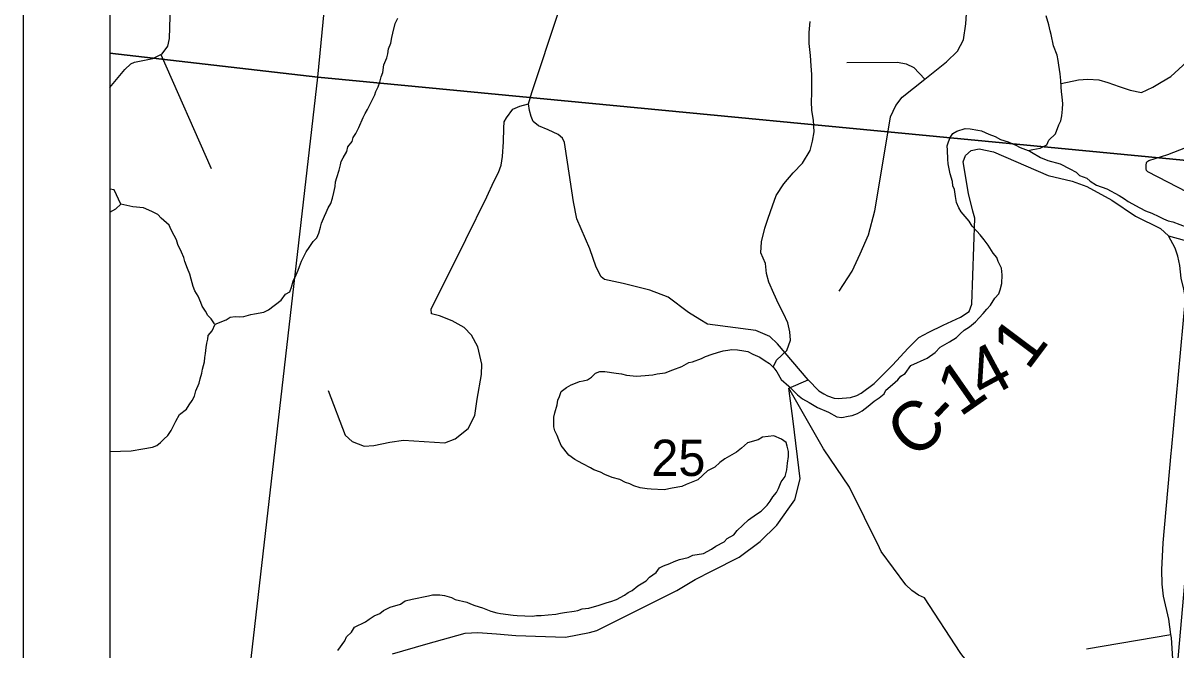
# Model space of a CAD drawing. Extents: x 0 to 34, y -2 to 22.
# Drawn here: x 2 to 3.329, y 18.423 to 19.146 of the extents above; entities that cross this region are included whole.
import ezdxf

# ---------------------------------------------------------------- set-up
doc = ezdxf.new("R2010")
doc.units = 0
for name, color, linetype in [('Default', 7, 'Continuous'), ('GM_X_County_Road', 7, 'Continuous'), ('GM_X_County_Road_Text', 7, 'Continuous'), ('GM_X_Minor_Lake', 7, 'Continuous'), ('GM_X_Minor_River', 7, 'Continuous'), ('GM_X_Rail_Line', 7, 'Continuous'), ('GM_X_Section', 7, 'Continuous'), ('GM_X_Section_Text', 7, 'Continuous'), ('GM_X_Township_Road', 7, 'Continuous'), ('SH_Cut_Line', 7, 'Continuous'), ('SH_Data', 7, 'Continuous')]:
    doc.layers.add(name, color=color, linetype=linetype)

msp = doc.modelspace()

# ---------------------------------------------------------------- linework, layer by layer
at = {"layer": 'Default'}
for points in [[(2.1, 20.1369), (2.1, 19.1108), (2.3398, 19.083), (2.4387, 20.1012)], [(2.1, 19.1108), (2.1, 18.1402), (2.2302, 18.1283), (2.3398, 19.083)]]:
    msp.add_lwpolyline(points, close=True, dxfattribs=at)
at = {"layer": 'GM_X_County_Road'}
for p, q in [((2.883, 18.7247), (2.9052, 18.7343)), ((2.8877, 18.6867), (2.883, 18.7247))]:
    msp.add_line(p, q, dxfattribs=at)
for points in [[(2.1, 19.0714), (2.1174, 19.092), (2.1244, 19.0986), (2.1286, 19.1004), (2.1496, 19.1047), (2.1589, 19.1093), (2.1604, 19.11), (2.1668, 19.1189), (2.1689, 19.1276), (2.1712, 19.2042)], [(2.9052, 18.7343), (2.8698, 18.7757), (2.861, 18.7844), (2.8449, 18.791), (2.7891, 18.7985), (2.7801, 18.8037), (2.7671, 18.8117), (2.7438, 18.8295), (2.7225, 18.8375), (2.692, 18.8453), (2.6705, 18.8498), (2.6665, 18.8529), (2.6608, 18.8641), (2.6535, 18.8854), (2.6386, 18.9199), (2.6348, 18.9394), (2.6277, 18.985), (2.6241, 19.0078), (2.6218, 19.0128), (2.6171, 19.0171), (2.6053, 19.0224), (2.5942, 19.0272), (2.5883, 19.0321), (2.5859, 19.038), (2.584, 19.0447), (2.5829, 19.0523), (2.5867, 19.0654), (2.6175, 19.1582)], [(3.2954, 18.9847), (3.2957, 18.9857), (3.298, 18.9872), (3.3198, 18.9941), (3.3543, 19.0075), (3.3733, 19.0175), (3.3749, 19.0196), (3.3759, 19.0213), (3.3764, 19.0222)], [(2.9052, 18.7343), (2.9175, 18.7215), (2.9232, 18.7181), (2.9276, 18.716), (2.9353, 18.7132), (2.9398, 18.7126), (2.9539, 18.7138), (2.9613, 18.7163), (2.9662, 18.7187), (2.9813, 18.73), (3.0025, 18.7513), (3.0206, 18.7709), (3.0327, 18.783), (3.0443, 18.7891), (3.0609, 18.7973), (3.0809, 18.8066), (3.0906, 18.8131), (3.0939, 18.8213), (3.0975, 18.9207), (3.0951, 18.9288), (3.0901, 18.9491), (3.0837, 18.9854), (3.0866, 18.9929), (3.0932, 18.9988), (3.1024, 19.0004), (3.1189, 18.9972), (3.1817, 18.9697), (3.2096, 18.9631), (3.2265, 18.9572), (3.2551, 18.9415), (3.2826, 18.9228), (3.3113, 18.9086), (3.3205, 18.9003)], [(3.3715, 18.9091), (3.3743, 18.9185), (3.374, 18.9246), (3.3728, 18.9294), (3.3698, 18.934), (3.3693, 18.9347), (3.3678, 18.9363), (3.3542, 18.9444), (3.2968, 18.974), (3.2952, 18.9755), (3.295, 18.9775), (3.2948, 18.9828), (3.2951, 18.9838), (3.2954, 18.9847)], [(3.3205, 18.9003), (3.3385, 18.8951), (3.3495, 18.8937), (3.3545, 18.8947), (3.3715, 18.9091)], [(3.324, 18.6527), (3.3401, 18.8282), (3.3382, 18.8386), (3.3352, 18.8516), (3.3338, 18.866), (3.3315, 18.8768), (3.3284, 18.886), (3.3205, 18.9003)], [(2.9873, 18.5407), (2.9529, 18.6106), (2.9227, 18.6546), (2.883, 18.7247)], [(2.7943, 18.5139), (2.8257, 18.53), (2.8499, 18.548), (2.869, 18.5667), (2.884, 18.588), (2.8896, 18.596), (2.896, 18.6203), (2.8877, 18.6867)], [(3.2876, 17.9648), (3.2993, 18.0896), (3.3169, 18.29), (3.3244, 18.3467), (3.3252, 18.3831), (3.3254, 18.4128), (3.3239, 18.4367), (3.3234, 18.4405), (3.3209, 18.4585), (3.3149, 18.4849), (3.3131, 18.4986), (3.3129, 18.5153), (3.3143, 18.5465), (3.3238, 18.6498), (3.324, 18.6527)], [(3.3169, 18.29), (3.2265, 18.2864), (3.219, 18.2885), (3.2101, 18.2938), (3.1687, 18.3312), (3.1088, 18.3855), (3.0822, 18.4172), (3.0803, 18.42), (3.0392, 18.4831), (3.0325, 18.486), (3.0247, 18.4912), (3.0177, 18.4979), (2.9894, 18.5364), (2.9873, 18.5407)], [(2.4259, 18.4185), (2.4645, 18.4294), (2.5099, 18.4421), (2.5243, 18.4429), (2.5459, 18.4413), (2.5682, 18.4397), (2.6023, 18.4382), (2.6254, 18.4377), (2.6532, 18.4428), (2.6617, 18.4452), (2.6662, 18.4474), (2.7539, 18.4914), (2.7749, 18.5039), (2.7943, 18.5139)]]:
    msp.add_lwpolyline(points, dxfattribs=at)
at = {"layer": 'GM_X_Minor_Lake'}
for points in [[(2.1129, 18.9369), (2.105, 18.9534), (2.1, 18.954)], [(2.1, 18.9275), (2.1071, 18.9313), (2.1129, 18.9369)]]:
    msp.add_lwpolyline(points, dxfattribs=at)
at = {"layer": 'GM_X_Minor_River'}
for points in [[(2.9511, 18.6922), (2.9557, 18.6932), (2.9619, 18.6956), (2.9673, 18.6985), (2.9743, 18.7039), (2.9813, 18.7098), (2.9871, 18.7134), (2.9926, 18.7181), (2.9947, 18.7222), (3.0025, 18.7288), (3.0084, 18.7343), (3.0119, 18.7384), (3.017, 18.7416), (3.0234, 18.7509), (3.0423, 18.7594), (3.0516, 18.7659), (3.0575, 18.7718), (3.068, 18.7779), (3.0761, 18.7829), (3.0804, 18.7873), (3.0851, 18.7917), (3.091, 18.7953), (3.098, 18.8011), (3.1023, 18.8059), (3.1071, 18.8107), (3.111, 18.8159), (3.1154, 18.8203), (3.1202, 18.8285), (3.1249, 18.8333), (3.1266, 18.8382), (3.1284, 18.8453), (3.1287, 18.8552), (3.1279, 18.8628), (3.1243, 18.8706), (3.1226, 18.8752), (3.1186, 18.8803), (3.1128, 18.8896), (3.1081, 18.8958), (3.1034, 18.9013), (3.0997, 18.9056), (3.0942, 18.9115), (3.0906, 18.9173), (3.0815, 18.9279), (3.079, 18.9326), (3.0762, 18.9387), (3.0749, 18.9456), (3.074, 18.9536), (3.0719, 18.9579), (3.0717, 18.9628), (3.069, 18.9717), (3.0667, 18.9832), (3.0661, 18.9885), (3.0657, 18.9992), (3.0655, 19.0041), (3.0668, 19.0086), (3.0689, 19.0135), (3.0721, 19.0183), (3.0767, 19.0208), (3.086, 19.0239), (3.092, 19.0237), (3.1007, 19.0219), (3.1049, 19.0214), (3.1134, 19.0173), (3.1206, 19.0147), (3.1269, 19.0115), (3.1359, 19.0085), (3.14, 19.0068), (3.1445, 19.0048), (3.1494, 19.002), (3.1587, 18.9986), (3.1641, 18.9996), (3.1725, 19.0012), (3.1802, 19.0051), (3.1827, 19.0107), (3.1902, 19.018), (3.1943, 19.0282), (3.1964, 19.033), (3.1977, 19.0387), (3.1984, 19.0463), (3.1986, 19.0527), (3.1981, 19.0603), (3.1972, 19.0668), (3.197, 19.0718), (3.1965, 19.0794), (3.1956, 19.087), (3.194, 19.097), (3.1935, 19.1023), (3.1921, 19.1084), (3.188, 19.1192), (3.1854, 19.1322), (3.184, 19.1365), (3.1827, 19.1434), (3.1797, 19.1537)], [(2.1, 18.6516), (2.1122, 18.6521), (2.1247, 18.6524), (2.1381, 18.6546), (2.1492, 18.6565), (2.1542, 18.6586), (2.1585, 18.6619), (2.1624, 18.6659), (2.1671, 18.6699), (2.1707, 18.6759), (2.1732, 18.6804), (2.176, 18.6867), (2.1805, 18.6942), (2.1886, 18.7004), (2.1915, 18.7056), (2.1951, 18.7104), (2.1975, 18.7156), (2.1993, 18.7217), (2.203, 18.7303), (2.2043, 18.7355), (2.206, 18.7419), (2.2069, 18.7465), (2.2091, 18.7551), (2.2097, 18.7601), (2.2102, 18.7646), (2.2112, 18.7714), (2.2118, 18.7767), (2.2131, 18.7812), (2.2136, 18.7854), (2.218, 18.7909), (2.2216, 18.7984), (2.234, 18.8033), (2.2386, 18.8066), (2.2444, 18.8071), (2.2497, 18.807), (2.2546, 18.8072), (2.2627, 18.8095), (2.2669, 18.8105), (2.2776, 18.8124), (2.283, 18.8149), (2.2974, 18.8262), (2.3026, 18.8332), (2.3076, 18.8357), (2.3093, 18.841), (2.3114, 18.8481), (2.3147, 18.8553), (2.3172, 18.8605), (2.3189, 18.865), (2.321, 18.871), (2.3263, 18.8818), (2.3299, 18.887), (2.3343, 18.8937), (2.3386, 18.8981), (2.3411, 18.9034), (2.3428, 18.9102), (2.3441, 18.9147), (2.3474, 18.9229), (2.3495, 18.927), (2.3516, 18.9327), (2.3548, 18.9375), (2.3569, 18.9435), (2.3583, 18.9503), (2.36, 18.9571), (2.3602, 18.9624), (2.3619, 18.9677), (2.3645, 18.9759), (2.3658, 18.982), (2.3667, 18.9861), (2.3691, 18.9902), (2.3732, 18.9973), (2.3745, 19.003), (2.3793, 19.0092), (2.3806, 19.0138), (2.3838, 19.0182), (2.387, 19.0253), (2.392, 19.0366), (2.3944, 19.0414), (2.3973, 19.0459), (2.4013, 19.0545), (2.4054, 19.0627), (2.4067, 19.0668), (2.4095, 19.0721), (2.4112, 19.0773), (2.413, 19.0837), (2.4147, 19.0886), (2.4161, 19.0973), (2.4194, 19.1055), (2.4204, 19.1101), (2.4213, 19.1157), (2.4242, 19.1225), (2.4252, 19.1289), (2.4265, 19.1338), (2.4292, 19.1451), (2.432, 19.1511)], [(2.865, 18.7487), (2.8686, 18.757), (2.8806, 18.768), (2.8848, 18.7801), (2.8839, 18.7896), (2.8816, 18.7999), (2.8766, 18.8107), (2.8708, 18.8219), (2.8655, 18.8339), (2.8598, 18.8469), (2.857, 18.8569), (2.8558, 18.8683), (2.8505, 18.8807), (2.8512, 18.8932), (2.8551, 18.909), (2.8589, 18.9207), (2.8642, 18.935), (2.8683, 18.9467), (2.8771, 18.9601), (2.8877, 18.9727), (2.8987, 18.9842), (2.9075, 18.9988), (2.91, 19.0094), (2.9119, 19.0203), (2.9115, 19.0337), (2.9095, 19.0447), (2.9091, 19.055), (2.9094, 19.0645), (2.9093, 19.0759), (2.9092, 19.0862), (2.9087, 19.0961), (2.908, 19.1083), (2.9065, 19.122), (2.9064, 19.1346), (2.9076, 19.1475)], [(3.1967, 19.076), (3.2167, 19.0801), (3.2277, 19.0809), (3.2402, 19.0802), (3.2508, 19.0772), (3.2639, 19.0726), (3.2763, 19.0681), (3.2896, 19.0654), (3.3026, 19.0715), (3.3123, 19.0773), (3.3231, 19.0839), (3.3372, 19.0968), (3.3493, 19.1097), (3.3615, 19.1223), (3.3766, 19.134), (3.39, 19.1386), (3.4031, 19.1439)], [(3.1595, 18.9987), (3.1628, 18.9966), (3.1729, 18.9905), (3.1815, 18.9872), (3.1958, 18.9833), (3.207, 18.9775), (3.2141, 18.9735), (3.2181, 18.9699), (3.2264, 18.9666), (3.2304, 18.9634), (3.2375, 18.9586), (3.2495, 18.9544), (3.2636, 18.9467), (3.27, 18.9431), (3.274, 18.9399), (3.2874, 18.9326), (3.2941, 18.9289), (3.3013, 18.9264), (3.3095, 18.9227), (3.3147, 18.9198), (3.3203, 18.9177), (3.3256, 18.9164), (3.3417, 18.9102)], [(2.1547, 18.9254), (2.1484, 18.9283), (2.1387, 18.9324), (2.1265, 18.9338), (2.1129, 18.9369)], [(2.2209, 18.7988), (2.2169, 18.8047), (2.2129, 18.8086), (2.2104, 18.8133), (2.2064, 18.8191), (2.205, 18.8233), (2.2019, 18.8307), (2.1979, 18.8369), (2.1962, 18.8419), (2.1938, 18.8503), (2.1921, 18.8561), (2.1897, 18.8626), (2.1866, 18.8707), (2.1852, 18.8753), (2.1828, 18.8815), (2.1785, 18.8904), (2.1768, 18.8958), (2.1743, 18.9008), (2.1707, 18.907), (2.1683, 18.9124), (2.1594, 18.9207), (2.1554, 18.925), (2.1547, 18.9254)], [(2.8741, 18.6166), (2.8785, 18.6229), (2.8806, 18.6304), (2.8813, 18.638), (2.8823, 18.6459), (2.8825, 18.6516), (2.8808, 18.6578), (2.8798, 18.662), (2.8743, 18.666), (2.8657, 18.6697), (2.8527, 18.6682), (2.8477, 18.665), (2.8354, 18.6616), (2.8283, 18.6554), (2.8225, 18.651), (2.8089, 18.6431), (2.8035, 18.6388), (2.7976, 18.6337), (2.7891, 18.6294), (2.7781, 18.6191), (2.7646, 18.6135), (2.7596, 18.6114), (2.7482, 18.6095), (2.739, 18.6076), (2.7242, 18.6081), (2.7197, 18.6086), (2.7113, 18.6097), (2.7042, 18.6122), (2.6994, 18.6143), (2.6945, 18.6159), (2.6881, 18.6192), (2.6791, 18.6218), (2.6709, 18.6251), (2.6657, 18.628), (2.6582, 18.6305), (2.6541, 18.6329), (2.6455, 18.6374), (2.6403, 18.6402), (2.6362, 18.6423), (2.6291, 18.6475), (2.6204, 18.6584), (2.6176, 18.665), (2.6159, 18.67), (2.613, 18.6754), (2.612, 18.68), (2.6118, 18.6849), (2.612, 18.6914), (2.613, 18.6963), (2.6156, 18.7053), (2.6165, 18.711), (2.6186, 18.7151), (2.6203, 18.7208), (2.6265, 18.7255), (2.6319, 18.7283), (2.6369, 18.7304), (2.6415, 18.7322), (2.6458, 18.7332), (2.6507, 18.7342), (2.6554, 18.7374), (2.6601, 18.7418), (2.6651, 18.7439), (2.6708, 18.7437), (2.6837, 18.7421), (2.6901, 18.7412), (2.6957, 18.7398), (2.7074, 18.7386), (2.7173, 18.7391), (2.7215, 18.7397), (2.7261, 18.7399), (2.7311, 18.7413), (2.7402, 18.7425), (2.7491, 18.7456), (2.7595, 18.7498), (2.7676, 18.7541), (2.7718, 18.755), (2.7822, 18.7589), (2.7868, 18.761), (2.7945, 18.7638), (2.8006, 18.7658), (2.8072, 18.7675), (2.8125, 18.7685), (2.8171, 18.7691), (2.8235, 18.7688), (2.8311, 18.7678), (2.8356, 18.7669), (2.8412, 18.764), (2.8494, 18.7603), (2.8554, 18.756), (2.8606, 18.7531), (2.8657, 18.748), (2.869, 18.7433), (2.874, 18.7348), (2.8828, 18.7269), (2.8927, 18.717), (2.8986, 18.7123), (2.9065, 18.7082), (2.9158, 18.7025), (2.9285, 18.6968), (2.9382, 18.6915), (2.9438, 18.6909), (2.9511, 18.6922)], [(2.3628, 18.4222), (2.3711, 18.4333), (2.3728, 18.4378), (2.3787, 18.4433), (2.382, 18.4493), (2.3947, 18.4553), (2.399, 18.4585), (2.4048, 18.4621), (2.4113, 18.465), (2.4156, 18.4682), (2.4234, 18.4721), (2.4353, 18.4755), (2.4407, 18.4795), (2.4487, 18.4815), (2.4675, 18.4851), (2.4721, 18.4864), (2.4804, 18.4865), (2.4857, 18.4856), (2.494, 18.4834), (2.4981, 18.481), (2.5116, 18.4778), (2.5158, 18.4762), (2.521, 18.4741), (2.5296, 18.4715), (2.5394, 18.4677), (2.5461, 18.4656), (2.5503, 18.4647), (2.565, 18.4631), (2.5696, 18.4625), (2.5874, 18.4619), (2.592, 18.4625), (2.5973, 18.4627), (2.6053, 18.4632), (2.6144, 18.464), (2.6198, 18.4653), (2.6244, 18.4659), (2.6354, 18.4675), (2.6396, 18.4685), (2.6446, 18.4702), (2.6523, 18.4711), (2.6641, 18.4745), (2.6734, 18.4776), (2.6776, 18.4789), (2.6841, 18.481), (2.6934, 18.486), (2.6977, 18.4889), (2.7023, 18.4914), (2.7086, 18.4969), (2.7183, 18.5026), (2.7222, 18.5067), (2.73, 18.5121), (2.7336, 18.5177), (2.7382, 18.5198), (2.7455, 18.5226), (2.7506, 18.5247), (2.7567, 18.5271), (2.767, 18.5294), (2.7721, 18.5323), (2.7843, 18.5342), (2.7936, 18.5391), (2.7986, 18.5424), (2.8083, 18.5474), (2.8118, 18.5514), (2.8196, 18.5557), (2.8232, 18.5606), (2.8365, 18.573), (2.8455, 18.5792), (2.8509, 18.5828), (2.858, 18.5898), (2.8612, 18.5942), (2.8644, 18.5994), (2.8687, 18.6042), (2.8708, 18.6091), (2.8741, 18.6166)]]:
    msp.add_lwpolyline(points, dxfattribs=at)
at = {"layer": 'GM_X_Rail_Line'}
msp.add_lwpolyline([(7.5809, 20.9), (2.1, 20.9), (2.1, 18.1368), (2.3446, 18.1102), (2.9298, 18.0171), (3.2869, 17.9604), (3.6832, 17.9108)], dxfattribs=at)
at = {"layer": 'GM_X_Section'}
for points in [[(3.4541, 19.9967), (3.3818, 18.9832), (2.3398, 19.083), (2.4387, 20.1012)], [(2.3398, 19.083), (3.3818, 18.9832), (3.2914, 17.96), (2.2302, 18.1283)]]:
    msp.add_lwpolyline(points, close=True, dxfattribs=at)
at = {"layer": 'GM_X_Township_Road'}
for p, q in [((2.1589, 19.1093), (2.2168, 18.9779)), ((3.2261, 18.4243), (3.3234, 18.4405))]:
    msp.add_line(p, q, dxfattribs=at)
for points in [[(2.9408, 18.8365), (2.956, 18.8596), (2.965, 18.8795), (2.9747, 18.9014), (2.9819, 18.9292), (2.9987, 19.0279), (3, 19.0374), (3.0064, 19.0505), (3.0135, 19.06), (3.0396, 19.0809), (3.0648, 19.1007), (3.0772, 19.1133), (3.0844, 19.1261), (3.0868, 19.1448), (3.092, 19.221)], [(2.9498, 19.1002), (3.008, 19.1006), (3.018, 19.0985), (3.0268, 19.0944), (3.0396, 19.0809)], [(2.3518, 18.7219), (2.3712, 18.6706), (2.3796, 18.663), (2.3931, 18.6576), (2.4046, 18.6587), (2.423, 18.6625), (2.4385, 18.6648), (2.4862, 18.6615), (2.4982, 18.6663), (2.513, 18.6783), (2.5207, 18.6931), (2.5237, 18.712), (2.5286, 18.7403), (2.5291, 18.7525), (2.5242, 18.7724), (2.5171, 18.7857), (2.5084, 18.7946), (2.4949, 18.8023), (2.4801, 18.8079), (2.4709, 18.8102), (2.4704, 18.8158), (2.5105, 18.8961), (2.5348, 18.9452), (2.5429, 18.9628), (2.5482, 18.9731), (2.5513, 18.9819), (2.5526, 18.9919), (2.554, 19.0086), (2.5542, 19.0245), (2.5548, 19.0316), (2.5574, 19.0362), (2.5645, 19.0461), (2.5727, 19.0498), (2.5829, 19.0523)]]:
    msp.add_lwpolyline(points, dxfattribs=at)
at = {"layer": 'SH_Cut_Line'}
msp.add_lwpolyline([(8.9, 20.9), (2.1, 20.9), (2.1, 16.3648), (2.1342, 16.3571), (2.2291, 16.3515), (2.5217, 16.3621), (2.6166, 16.3275), (2.9069, 16.2111), (3.202, 16.0321), (3.297, 15.9555), (3.6339, 15.5717)], dxfattribs=at)
at = {"layer": 'SH_Data'}
for p, q in [((2, 21), (2, 14)), ((2.1, 20.9), (2.1, 14.1))]:
    msp.add_line(p, q, dxfattribs=at)

# ---------------------------------------------------------------- texts
at = {"layer": 'GM_X_County_Road_Text'}
for s, rotation, p in [('1', 53.1852, (3.1584, 18.7439)), ('4', 28.3725, (3.1075, 18.7099)), ('1', 34.9552, (3.0802, 18.6907)), ('C', 41.3144, (3.0273, 18.641)), ('-', 46.584, (3.0665, 18.6758))]:
    msp.add_text(s, height=0.0568, rotation=rotation, dxfattribs=at).set_placement(p)
at = {"layer": 'GM_X_Section_Text'}
msp.add_text('25', height=0.04186, rotation=0, dxfattribs=at).set_placement((2.7244, 18.6234))

doc.saveas('drawing.dxf')
